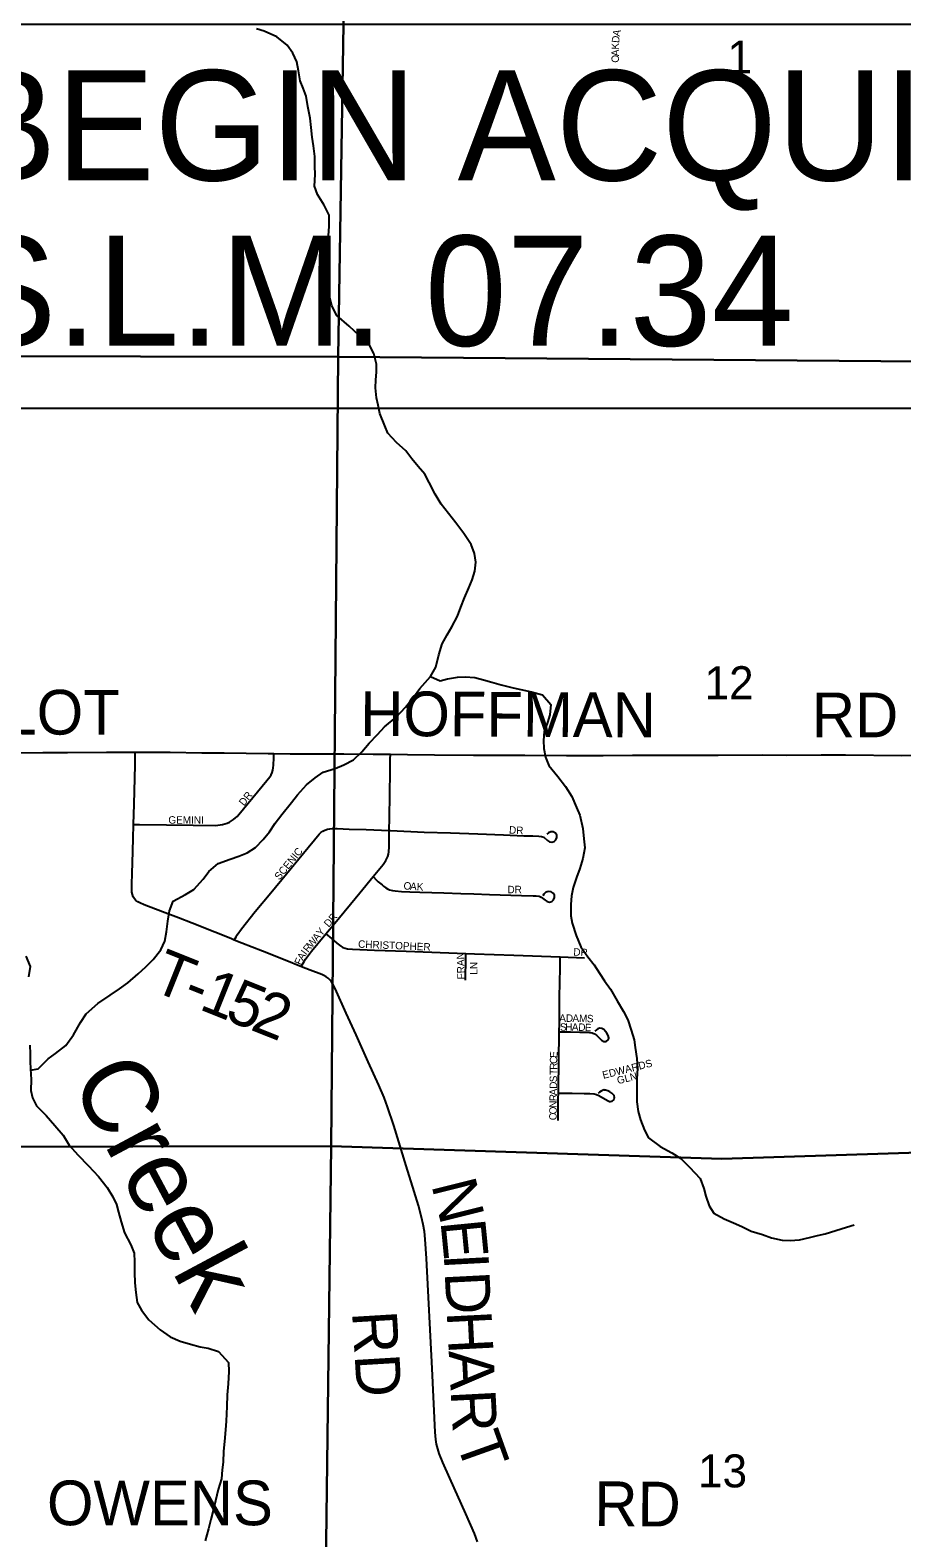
# Model space of a CAD drawing. Extents: x -97 to 34, y -21 to 22.
# Drawn here: x 7.185 to 8.293, y 14.954 to 16.869 of the extents above; entities that cross this region are included whole.
import ezdxf

# ---------------------------------------------------------------- set-up
doc = ezdxf.new("R2010")
doc.units = 0
for name, color, linetype in [('GM_X_County_Road', 7, 'Continuous'), ('GM_X_County_Road_Text', 7, 'Continuous'), ('GM_X_Minor_River', 7, 'Continuous'), ('GM_X_Minor_River_Text', 7, 'Continuous'), ('GM_X_Section', 7, 'Continuous'), ('GM_X_Section_Text', 7, 'Continuous'), ('GM_X_Township_Road', 7, 'Continuous'), ('GM_X_Township_Road_Text', 7, 'Continuous'), ('GM_X_Township_Subdivision', 7, 'Continuous'), ('GM_X_Township_Subdivision_Text', 7, 'Continuous'), ('SH_Text', 7, 'Continuous')]:
    doc.layers.add(name, color=color, linetype=linetype)

msp = doc.modelspace()

# ---------------------------------------------------------------- linework, layer by layer
at = {"layer": 'GM_X_County_Road'}
for points in [[(7.0672, 15.9528), (7.0836, 15.9526), (7.1333, 15.9518), (7.1644, 15.9517), (7.2017, 15.9518), (7.2328, 15.9521), (7.2825, 15.9526), (7.3074, 15.9525), (7.3187, 15.9525)], [(7.3187, 15.9525), (7.3633, 15.9524), (7.4037, 15.9517), (7.4317, 15.9514), (7.4876, 15.9509), (7.4952, 15.9507)], [(7.4952, 15.9507), (7.5156, 15.9503), (7.5405, 15.9503), (7.584, 15.9503), (7.6213, 15.95), (7.6431, 15.9497)], [(7.6431, 15.9497), (7.6648, 15.9493), (7.699, 15.9492), (7.7487, 15.9488), (7.786, 15.9486), (7.814, 15.9485), (7.8668, 15.9481), (7.9134, 15.9483), (7.9507, 15.9485), (7.9849, 15.9486), (8.016, 15.9486), (8.0595, 15.9487), (8.1155, 15.9489), (8.1466, 15.9488), (8.1901, 15.9491), (8.2211, 15.9491), (8.2926, 15.9482), (8.3175, 15.9487), (8.3356, 15.949)]]:
    msp.add_lwpolyline(points, dxfattribs=at)
at = {"layer": 'GM_X_Minor_River'}
for points in [[(7.5589, 16.6471), (7.5504, 16.6609), (7.5468, 16.6715), (7.5474, 16.6863), (7.5471, 16.6969), (7.5469, 16.7091), (7.5452, 16.7227), (7.5438, 16.7334), (7.5425, 16.7459), (7.5411, 16.7576), (7.5383, 16.7725), (7.5362, 16.7858), (7.5322, 16.7957), (7.5285, 16.8052), (7.5264, 16.8177), (7.5243, 16.8291), (7.5192, 16.8402), (7.5121, 16.8505), (7.499, 16.8609), (7.4828, 16.868), (7.473, 16.8712)], [(7.1858, 15.5486), (7.1955, 15.5503), (7.2082, 15.5627), (7.2177, 15.5698), (7.2308, 15.5798), (7.2404, 15.5933), (7.2494, 15.6091), (7.2567, 15.62), (7.2713, 15.6331), (7.287, 15.6438), (7.2988, 15.652), (7.3095, 15.6594), (7.3226, 15.671), (7.3322, 15.6796), (7.3418, 15.6889), (7.3514, 15.7013), (7.3565, 15.7122), (7.3585, 15.7243), (7.3602, 15.7376), (7.3623, 15.7508), (7.367, 15.7633), (7.3827, 15.7718), (7.3934, 15.7781), (7.4053, 15.7912), (7.4126, 15.8009), (7.4242, 15.811), (7.4394, 15.8165), (7.4504, 15.8205), (7.4611, 15.8245), (7.4718, 15.8312), (7.4814, 15.8413), (7.4895, 15.8514), (7.4965, 15.8623), (7.5053, 15.8732), (7.5173, 15.8885), (7.525, 15.8983), (7.5365, 15.911), (7.5476, 15.92), (7.5576, 15.927), (7.5728, 15.9317), (7.5839, 15.9365), (7.5961, 15.9428), (7.6068, 15.9529), (7.6161, 15.9637), (7.6268, 15.975), (7.6357, 15.9847), (7.6502, 15.997), (7.6622, 16.0097), (7.6726, 16.0221), (7.6803, 16.0333), (7.6941, 16.0487), (7.7007, 16.0604), (7.7044, 16.0762), (7.7087, 16.0902), (7.715, 16.1015), (7.7212, 16.1116), (7.7282, 16.1252), (7.7325, 16.1365), (7.7372, 16.1485), (7.7427, 16.161), (7.747, 16.1715), (7.7502, 16.1821), (7.7515, 16.1938), (7.7501, 16.2048), (7.7457, 16.2163), (7.7364, 16.23), (7.7264, 16.2438), (7.7171, 16.2557), (7.7074, 16.2676), (7.7, 16.2802), (7.6923, 16.2951), (7.6867, 16.3054), (7.6782, 16.3154), (7.6703, 16.3249), (7.6625, 16.3353), (7.6509, 16.3457), (7.6397, 16.3576), (7.6361, 16.3671), (7.6295, 16.3827), (7.6274, 16.393), (7.6256, 16.4025), (7.6243, 16.415), (7.6244, 16.4252), (7.6253, 16.4351), (7.6254, 16.4453), (7.6222, 16.4586), (7.6159, 16.4701), (7.6036, 16.4816), (7.5909, 16.4935), (7.5752, 16.507), (7.5685, 16.5192), (7.566, 16.5299), (7.5639, 16.5428), (7.5626, 16.5595), (7.5624, 16.5697), (7.5626, 16.5845), (7.5632, 16.5974), (7.5645, 16.6087), (7.5654, 16.6201), (7.5652, 16.6345), (7.5589, 16.6471)], [(7.6941, 16.0487), (7.7062, 16.0428), (7.7157, 16.0454), (7.7282, 16.0478), (7.7381, 16.0481), (7.7502, 16.0472), (7.7615, 16.0444), (7.7721, 16.0412), (7.7838, 16.038), (7.7989, 16.034), (7.8087, 16.032), (7.8223, 16.0291), (7.8362, 16.0251), (7.8467, 16.0129), (7.8457, 16), (7.8426, 15.9902), (7.8386, 15.9785), (7.8377, 15.9671), (7.8379, 15.9569), (7.8401, 15.9459), (7.8445, 15.9356), (7.8556, 15.9214), (7.8657, 15.9088), (7.8734, 15.8962), (7.8793, 15.8821), (7.8837, 15.8725), (7.8876, 15.8554), (7.889, 15.8425), (7.89, 15.8307), (7.8875, 15.8175), (7.8839, 15.8047), (7.8796, 15.7934), (7.8752, 15.7805), (7.8732, 15.7699), (7.8723, 15.759), (7.8725, 15.7446), (7.8742, 15.7351), (7.8789, 15.7195), (7.8852, 15.705), (7.8937, 15.6924), (7.9019, 15.6824), (7.9086, 15.6717), (7.9149, 15.6621), (7.9227, 15.6514), (7.9312, 15.6365), (7.939, 15.6231), (7.9445, 15.6124), (7.9488, 15.5995), (7.9528, 15.5869), (7.9542, 15.5774), (7.9563, 15.5634), (7.9569, 15.5505), (7.9563, 15.5376), (7.9561, 15.5228), (7.9563, 15.5081), (7.958, 15.4959), (7.9609, 15.4853), (7.966, 15.4723), (7.9708, 15.4624), (7.9858, 15.4516), (8.0005, 15.4434), (8.0121, 15.4364), (8.0229, 15.4253), (8.0364, 15.4111), (8.0411, 15.3981), (8.044, 15.3886), (8.048, 15.3764), (8.0539, 15.3669), (8.0671, 15.3595), (8.0791, 15.3544), (8.0897, 15.3501), (8.1013, 15.3439), (8.1157, 15.3399), (8.1274, 15.3356), (8.1406, 15.3327), (8.1508, 15.3322), (8.1629, 15.3332), (8.1755, 15.336), (8.1857, 15.3385), (8.1952, 15.3407), (8.2089, 15.3447), (8.2226, 15.349), (8.2321, 15.3519)], [(7.1801, 15.6931), (7.1856, 15.6801), (7.1835, 15.6672)], [(7.1849, 15.5801), (7.1855, 15.5691), (7.1854, 15.5596), (7.1857, 15.5501), (7.1866, 15.5368), (7.1864, 15.5228), (7.1885, 15.5133), (7.1937, 15.503), (7.2057, 15.4911), (7.2168, 15.4784), (7.2273, 15.4658), (7.2351, 15.4532), (7.2462, 15.4409), (7.2597, 15.4271), (7.2724, 15.4136), (7.2832, 15.3994), (7.2906, 15.3876), (7.295, 15.3777), (7.2975, 15.3682), (7.3011, 15.356), (7.3055, 15.3419), (7.3132, 15.3266), (7.3176, 15.316), (7.3182, 15.305), (7.318, 15.2917), (7.3186, 15.2784)], [(7.3186, 15.2784), (7.3196, 15.2663), (7.3213, 15.2534), (7.3268, 15.2435), (7.3361, 15.2312), (7.3507, 15.2185), (7.3635, 15.21), (7.3759, 15.2045), (7.3891, 15.2005), (7.4015, 15.197), (7.4114, 15.1953), (7.4246, 15.1913), (7.4373, 15.1771), (7.4379, 15.1658), (7.4369, 15.1499), (7.4359, 15.1362), (7.4353, 15.1215), (7.4343, 15.1029), (7.4334, 15.0915), (7.4324, 15.0768), (7.4311, 15.0647), (7.4306, 15.0507), (7.4293, 15.0408), (7.4284, 15.0295), (7.4244, 15.0159), (7.4208, 15.0015), (7.418, 14.9894), (7.4148, 14.9777), (7.412, 14.966), (7.4076, 14.9505)]]:
    msp.add_lwpolyline(points, dxfattribs=at)
at = {"layer": 'GM_X_Section'}
for points in [[(7.5928, 17.458), (7.5768, 16.4545), (6.5713, 16.4562), (6.5942, 17.463)], [(8.6036, 17.4499), (8.5841, 16.4464), (7.5768, 16.4545), (7.5928, 17.458)], [(6.5713, 16.4562), (7.5768, 16.4545), (7.5679, 15.4518), (6.5605, 15.4504)], [(7.5768, 16.4545), (8.5841, 16.4464), (8.5658, 15.452), (8.0641, 15.4358), (7.5679, 15.4518)], [(6.5605, 15.4504), (7.5679, 15.4518), (7.5552, 14.4456), (6.5304, 14.4478)], [(7.5679, 15.4518), (8.0641, 15.4358), (8.5658, 15.452), (8.566, 15.4224), (8.5572, 14.4394), (7.5552, 14.4456)]]:
    msp.add_lwpolyline(points, close=True, dxfattribs=at)
at = {"layer": 'GM_X_Township_Road'}
for points in [[(7.3168, 15.8605), (7.3174, 15.8862), (7.3187, 15.9359), (7.3187, 15.9453), (7.3187, 15.9525)], [(7.4447, 15.7138), (7.4402, 15.7157), (7.42, 15.7236), (7.3913, 15.7352), (7.3739, 15.742), (7.3535, 15.7497), (7.3303, 15.7585), (7.3247, 15.7609), (7.3221, 15.7624), (7.3197, 15.7642), (7.3178, 15.7663), (7.3164, 15.7688), (7.3154, 15.7716), (7.3148, 15.7745), (7.3146, 15.7775), (7.3145, 15.7837), (7.3151, 15.7992), (7.3154, 15.8116), (7.3164, 15.8427), (7.3168, 15.8605)], [(7.5302, 15.6799), (7.5094, 15.6881), (7.4805, 15.6995), (7.4545, 15.7096), (7.4447, 15.7138)], [(7.7539, 14.9494), (7.7499, 14.9602), (7.7389, 14.9849), (7.7185, 15.0303), (7.7097, 15.0502), (7.705, 15.0616), (7.7032, 15.0675), (7.7018, 15.0734), (7.7009, 15.0795), (7.7001, 15.0888), (7.6961, 15.1695), (7.6888, 15.3092), (7.6873, 15.334), (7.6864, 15.3434), (7.6848, 15.3526), (7.6827, 15.3617), (7.6787, 15.3768), (7.6732, 15.3946), (7.6633, 15.4272), (7.6475, 15.4782), (7.6395, 15.5021), (7.6351, 15.5137), (7.6282, 15.5295), (7.6148, 15.559), (7.5994, 15.5934), (7.5871, 15.621), (7.573, 15.6522), (7.5701, 15.6578), (7.5684, 15.6605), (7.5664, 15.663), (7.5641, 15.6652), (7.5615, 15.6672), (7.5587, 15.6688), (7.5559, 15.6701), (7.5413, 15.6756), (7.5302, 15.6799)]]:
    msp.add_lwpolyline(points, dxfattribs=at)
at = {"layer": 'GM_X_Township_Subdivision'}
for points in [[(7.3168, 15.8605), (7.3245, 15.8604), (7.3586, 15.8599), (7.3927, 15.8596), (7.4207, 15.8594), (7.4269, 15.8599), (7.4299, 15.8604), (7.4329, 15.8612), (7.4358, 15.8622), (7.4387, 15.8635), (7.4413, 15.8651), (7.4439, 15.8668), (7.4463, 15.8688), (7.4486, 15.8709), (7.4507, 15.8732), (7.4862, 15.9163), (7.49, 15.9212), (7.4916, 15.9238), (7.4929, 15.9267), (7.4938, 15.9296), (7.4943, 15.9327), (7.4946, 15.9358), (7.4949, 15.9451), (7.4952, 15.9507)], [(7.6417, 15.8529), (7.6419, 15.8692), (7.6426, 15.9281), (7.6429, 15.9437), (7.6431, 15.9497)], [(7.4447, 15.7138), (7.4471, 15.7179), (7.4486, 15.7206), (7.454, 15.7281), (7.4715, 15.7499), (7.4913, 15.7738), (7.5112, 15.7977), (7.5328, 15.8242), (7.5525, 15.8481), (7.5547, 15.8503), (7.5573, 15.8521), (7.56, 15.8535), (7.563, 15.8544), (7.566, 15.8551), (7.5691, 15.8554), (7.5753, 15.8555), (7.5906, 15.8548), (7.6124, 15.8541), (7.6417, 15.8529)], [(7.6211, 15.7943), (7.6337, 15.8096), (7.6372, 15.8146), (7.6387, 15.8172), (7.6398, 15.82), (7.6406, 15.8229), (7.6411, 15.8258), (7.6414, 15.832), (7.6417, 15.8529)], [(7.6417, 15.8529), (7.6432, 15.8529), (7.686, 15.851), (7.7195, 15.85), (7.7543, 15.8485), (7.7867, 15.8474), (7.8126, 15.8462), (7.8241, 15.846), (7.8315, 15.8458), (7.8351, 15.8454), (7.8378, 15.8444), (7.8425, 15.8403), (7.8452, 15.8387), (7.8482, 15.8383), (7.8512, 15.8391), (7.8534, 15.8412), (7.8546, 15.8441), (7.8543, 15.8471), (7.8527, 15.8497), (7.85, 15.8512), (7.847, 15.8513), (7.8441, 15.8501), (7.8416, 15.8483)], [(7.5612, 15.7217), (7.5726, 15.7354), (7.6042, 15.7736), (7.6211, 15.7943)], [(7.6211, 15.7943), (7.6255, 15.79), (7.6277, 15.7879), (7.6325, 15.7839), (7.6343, 15.7823), (7.6372, 15.7802), (7.6393, 15.7788), (7.642, 15.7775), (7.6457, 15.7765), (7.6493, 15.7761), (7.6572, 15.7753), (7.6677, 15.775), (7.6806, 15.7744), (7.7109, 15.7738), (7.7325, 15.7729), (7.7489, 15.7723), (7.7688, 15.7715), (7.8095, 15.7704), (7.8245, 15.77), (7.8282, 15.77), (7.8319, 15.7696), (7.8347, 15.7683), (7.8395, 15.7643), (7.8421, 15.7627), (7.8452, 15.762), (7.8481, 15.7627), (7.8503, 15.7648), (7.8515, 15.7677), (7.8514, 15.7708), (7.8498, 15.7734), (7.8473, 15.7751), (7.8442, 15.7754), (7.8421, 15.7752), (7.8402, 15.7742), (7.8382, 15.7721), (7.8369, 15.77)], [(7.5302, 15.6799), (7.5312, 15.6825), (7.5334, 15.6866), (7.5352, 15.6897), (7.5428, 15.6996), (7.5612, 15.7217)], [(7.5612, 15.7217), (7.5681, 15.7158), (7.5752, 15.7098), (7.5801, 15.7059), (7.5828, 15.7043), (7.5857, 15.7033), (7.5887, 15.7026), (7.5949, 15.7021), (7.6228, 15.7011), (7.6632, 15.6997), (7.7388, 15.6968)], [(7.7385, 15.6627), (7.7385, 15.6691), (7.7389, 15.6851), (7.7388, 15.6883), (7.7388, 15.6914), (7.7388, 15.6968)], [(7.7388, 15.6968), (7.7501, 15.6964), (7.7998, 15.6945), (7.8589, 15.6923)], [(7.8576, 15.5973), (7.8578, 15.6078), (7.8581, 15.6407), (7.8585, 15.6604), (7.8589, 15.6781), (7.8589, 15.6889), (7.8589, 15.6923)], [(7.8589, 15.6923), (7.8898, 15.6912)], [(7.8566, 15.5195), (7.8568, 15.5309), (7.857, 15.5539), (7.8572, 15.5676), (7.8575, 15.5891), (7.8576, 15.5973)], [(7.8576, 15.5973), (7.8622, 15.5973), (7.8719, 15.5973), (7.8839, 15.5969), (7.8931, 15.5967), (7.8962, 15.5965), (7.8993, 15.5958), (7.9022, 15.5948), (7.9047, 15.593), (7.9071, 15.5909), (7.9114, 15.5864), (7.9141, 15.5849), (7.9171, 15.585), (7.9196, 15.5869), (7.9205, 15.5886), (7.9205, 15.5897), (7.9198, 15.5926), (7.9182, 15.5953), (7.9163, 15.5978), (7.9141, 15.6001), (7.9115, 15.6016), (7.9085, 15.6018), (7.9064, 15.6012), (7.9047, 15.5998), (7.9029, 15.5979)], [(7.8562, 15.4844), (7.8563, 15.4875), (7.8562, 15.5126), (7.8566, 15.5195)], [(7.8566, 15.5195), (7.8653, 15.5193), (7.8738, 15.5192), (7.8894, 15.5189), (7.8964, 15.519), (7.902, 15.5184), (7.905, 15.5177), (7.9079, 15.5164), (7.9187, 15.5101), (7.9216, 15.5089), (7.9228, 15.5085), (7.9249, 15.5091), (7.9269, 15.5108), (7.9274, 15.5124), (7.9279, 15.514), (7.9274, 15.5163), (7.9261, 15.5176), (7.9245, 15.5191), (7.9219, 15.5208), (7.9191, 15.5223), (7.9162, 15.5233), (7.9151, 15.5233), (7.9143, 15.5234), (7.9126, 15.5228), (7.9107, 15.5217), (7.9089, 15.5205), (7.907, 15.5188)]]:
    msp.add_lwpolyline(points, dxfattribs=at)
at = {"layer": 'SH_Text'}
msp.add_lwpolyline([(7.0407, 16.8772), (9.1549, 16.8772), (9.1549, 16.3891), (7.0407, 16.3891)], close=True, dxfattribs=at)

# ---------------------------------------------------------------- texts
at = {"layer": 'GM_X_County_Road_Text'}
for s, rotation, p in [('SOMERLOT', 359.8757, (6.8728, 15.9755)), ('HOFFMAN', 359.7204, (7.6046, 15.973)), ('RD', 0, (8.1785, 15.9713)), ('OWENS', 0, (7.2068, 14.9705)), ('RD', 359.5457, (7.902, 14.9696))]:
    msp.add_text(s, height=0.05682, rotation=rotation, dxfattribs=at).set_placement(p)
at = {"layer": 'GM_X_Minor_River_Text'}
msp.add_text('Creek', height=0.09471, rotation=298.147, dxfattribs=at).set_placement((7.2356, 15.5356))
at = {"layer": 'GM_X_Section_Text'}
for s, height, p in [('1', 0.0419, (8.0714, 16.8144)), ('12', 0.04186, (8.0422, 16.0197)), ('13', 0.04186, (8.0339, 15.0186))]:
    msp.add_text(s, height=height, rotation=0, dxfattribs=at).set_placement(p)
at = {"layer": 'GM_X_Township_Road_Text'}
for s, height, rotation, p in [('T', 0.0568, 338.1994, (7.3374, 15.6508)), ('1', 0.0568, 338.2056, (7.3985, 15.6264)), ('-', 0.0568, 338.1913, (7.3768, 15.6351)), ('5', 0.0568, 338.2116, (7.431, 15.6134)), ('2', 0.0568, 338.2795, (7.4636, 15.6004)), ('N', 0.0568, 284.0142, (7.6949, 15.403)), ('E', 0.0568, 275.6492, (7.7066, 15.3566)), ('I', 0.0568, 273.0456, (7.7108, 15.315)), ('D', 0.0568, 272.9264, (7.712, 15.2917)), ('RD', 0.05682, 273.4533, (7.5943, 15.2414)), ('H', 0.0568, 272.9155, (7.7146, 15.2418)), ('A', 0.0568, 272.9119, (7.7171, 15.1919)), ('R', 0.0568, 273.0015, (7.7196, 15.1418)), ('T', 0.0568, 289.6445, (7.7256, 15.0776))]:
    msp.add_text(s, height=height, rotation=rotation, dxfattribs=at).set_placement(p)
at = {"layer": 'GM_X_Township_Subdivision_Text'}
for s, rotation, p in [('K', 88.9071, (7.9334, 16.8447)), ('D', 84.5721, (7.9336, 16.8529)), ('A', 77.4641, (7.9343, 16.8609)), ('O', 89.8251, (7.9334, 16.8281)), ('A', 89.8032, (7.9334, 16.8364)), ('DR', 51.3366, (7.4571, 15.8834)), ('GEMINI', 0, (7.361, 15.8616)), ('DR', 356.989, (7.7936, 15.8491)), ('SCENIC', 50.7924, (7.5021, 15.7892)), ('O', 355.7337, (7.6595, 15.7782)), ('A', 355.7473, (7.6678, 15.7776)), ('K', 357.2792, (7.6764, 15.777)), ('DR', 0, (7.7918, 15.7732)), ('DR', 48.8141, (7.5647, 15.7293)), ('Y', 50.2067, (7.5554, 15.7179)), ('R', 51.8332, (7.5386, 15.6973)), ('W', 50.3817, (7.5432, 15.7031)), ('A', 50.2, (7.5501, 15.7115)), ('CHRISTOPHER', 357.5903, (7.6019, 15.7041)), ('DR', 356.8222, (7.8753, 15.6941)), ('F', 66.3565, (7.5293, 15.6813)), ('A', 58.2078, (7.5319, 15.6871)), ('I', 53.1913, (7.5361, 15.694)), ('FRAN', 91.541, (7.7376, 15.6639)), ('LN', 90, (7.7537, 15.6698)), ('A', 359.6502, (7.8576, 15.6099)), ('S', 0, (7.8585, 15.5986)), ('H', 359.9563, (7.8652, 15.5986)), ('D', 359.6437, (7.866, 15.6099)), ('A', 359.2786, (7.8735, 15.5986)), ('A', 359.6284, (7.8743, 15.6098)), ('D', 358.2511, (7.8817, 15.5985)), ('M', 358.3785, (7.8826, 15.6097)), ('E', 357.0475, (7.89, 15.5982)), ('S', 356.993, (7.8925, 15.6095)), ('E', 86.3095, (7.8551, 15.5638)), ('T', 89.3044, (7.8549, 15.5423)), ('C', 89.32, (7.855, 15.5565)), ('R', 89.3288, (7.855, 15.549)), ('EDWARDS', 14.2356, (7.9137, 15.5374)), ('S', 89.317, (7.8548, 15.5331)), ('D', 89.3285, (7.8547, 15.5248)), ('GLN', 14.0362, (7.9322, 15.5306)), ('R', 89.3173, (7.8545, 15.509)), ('A', 89.317, (7.8546, 15.5165)), ('C', 89.32, (7.8542, 15.4848)), ('O', 89.3285, (7.8543, 15.4923)), ('N', 89.3224, (7.8544, 15.5006))]:
    msp.add_text(s, height=0.00947, rotation=rotation, dxfattribs=at).set_placement(p)
at = {"layer": 'SH_Text'}
for s, p in [('BEGIN ACQUISITION', (7.0938, 16.6785)), ('S.L.M. 07.34', (7.0938, 16.4685))]:
    msp.add_text(s, height=0.14, dxfattribs=at).set_placement(p)

doc.saveas('drawing.dxf')
